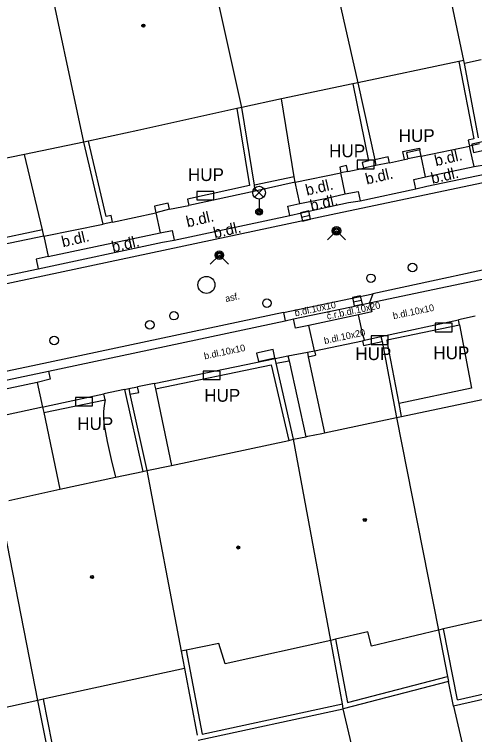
# Model space of a CAD drawing. Extents: x -596229 to -595156, y -1161237 to -1159376.
# Drawn here: x -595714.95 to -595687.89, y -1161008.44 to -1160966.09 of the extents above; entities that cross this region are included whole.
import ezdxf

# ---------------------------------------------------------------- set-up
doc = ezdxf.new("R2010")
doc.units = 0
for name, color, linetype in [('DOP - kresba z DSPS bez souradnic', 7, 'Continuous'), ('DOP - rozhrani ploch obecne', 7, 'Continuous'), ('Level 24', 7, 'Continuous'), ('Level 27', 7, 'Continuous'), ('Level 28', 7, 'Continuous'), ('Level 31', 7, 'Continuous'), ('Level 33', 7, 'Continuous'), ('Level 39', 7, 'Continuous'), ('plynovod - povrch.  znaky - PRIS skut. velikost', 7, 'Continuous'), ('Specificka linie pasportu komunikaci', 7, 'Continuous'), ('TM - budovy zdene_ betonove - VP', 7, 'Continuous'), ('TM - komunikace - VP', 7, 'Continuous'), ('TM - letecke snimky - pomocna linie', 7, 'Continuous'), ('TM - plot drateny_ kovovy - VP', 7, 'Continuous'), ('TM - plot dreveny - VP', 7, 'Continuous'), ('TM - plot zdeny_ ohradni zed - VP', 7, 'Continuous'), ('TM - podezdivka plotu - VP', 7, 'Continuous'), ('TM - popis objektu', 7, 'Continuous'), ('TM - popis povrchu', 7, 'Continuous'), ('TM - rozhrani mezi zpev. plochami mezi sebou - VP', 7, 'Continuous'), ('TM - rozhrani ploch obecne - VP', 7, 'Continuous'), ('TM - vjezd na pozemek', 7, 'Continuous')]:
    doc.layers.add(name, color=color, linetype=linetype)

msp = doc.modelspace()

# ---------------------------------------------------------------- linework, layer by layer
at = {"layer": 'DOP - kresba z DSPS bez souradnic'}
for points in [[(-595688.9, -1161006.41), (-595689.72, -1161002.23)], [(-595696.06, -1161002.84), (-595695.37, -1161006.56)], [(-595704.85, -1161003.47), (-595703.91, -1161008.41)], [(-595688.9, -1161006.41), (-595679.06, -1161004.17)], [(-595695.37, -1161006.56), (-595689.48, -1161005.02)], [(-595713.27, -1161006.37), (-595712.5, -1161010.25)], [(-595703.91, -1161008.41), (-595695.66, -1161006.64)]]:
    msp.add_lwpolyline(points, dxfattribs=at)
at = {"layer": 'DOP - rozhrani ploch obecne'}
for points in [[(-595690.01, -1161002.3), (-595689.48, -1161005.02)], [(-595695.66, -1161006.64), (-595696.35, -1161002.91)], [(-595704.95, -1161004.56), (-595704.21, -1161008.48)], [(-595679, -1161004.47), (-595689.13, -1161006.77)], [(-595689.48, -1161005.02), (-595689.42, -1161005.32)], [(-595689.42, -1161005.32), (-595695.61, -1161006.93)], [(-595689.13, -1161006.77), (-595689.42, -1161005.32)], [(-595712.81, -1161010.26), (-595713.57, -1161006.43)], [(-595695.61, -1161006.93), (-595695.66, -1161006.64)], [(-595689.13, -1161006.77), (-595685.09, -1161024.14)], [(-595704.15, -1161008.77), (-595695.61, -1161006.93)], [(-595691.15, -1161025.87), (-595695.61, -1161006.93)]]:
    msp.add_lwpolyline(points, dxfattribs=at)
at = {"layer": 'Level 24'}
for points in [[(-595687.944, -1160974.213), (-595686.968, -1160973.995), (-595687.076, -1160973.507), (-595688.052, -1160973.725)], [(-595694.798, -1160975.169), (-595693.798, -1160975.169), (-595693.798, -1160974.669), (-595694.798, -1160974.669)], [(-595704.218, -1160976.999), (-595703.218, -1160976.999), (-595703.218, -1160976.499), (-595704.218, -1160976.499)], [(-595690.198, -1160984.749), (-595689.198, -1160984.749), (-595689.198, -1160984.249), (-595690.198, -1160984.249)], [(-595693.978, -1160985.499), (-595692.978, -1160985.499), (-595692.978, -1160984.999), (-595693.978, -1160984.999)], [(-595700.604, -1160986.503), (-595699.628, -1160986.285), (-595699.736, -1160985.797), (-595700.712, -1160986.015)], [(-595703.858, -1160987.569), (-595702.858, -1160987.569), (-595702.858, -1160987.069), (-595703.858, -1160987.069)], [(-595711.358, -1160989.119), (-595710.358, -1160989.119), (-595710.358, -1160988.619), (-595711.358, -1160988.619)]]:
    msp.add_lwpolyline(points, close=True, dxfattribs=at)
at = {"layer": 'Level 27'}
for p, q in [((-595698.074, -1160978.006), (-595697.586, -1160977.894)), ((-595695.025, -1160982.992), (-595694.535, -1160982.888))]:
    msp.add_line(p, q, dxfattribs=at)
for points in [[(-595698.017, -1160978.25), (-595697.53, -1160978.137), (-595697.643, -1160977.65), (-595698.13, -1160977.763)], [(-595694.973, -1160983.236), (-595694.484, -1160983.133), (-595694.587, -1160982.644), (-595695.076, -1160982.747)]]:
    msp.add_lwpolyline(points, close=True, dxfattribs=at)
msp.add_circle((-595703.66, -1160982), 0.5, dxfattribs=at)
at = {"layer": 'Level 28'}
for centre in [(-595691.54, -1160980.97), (-595693.98, -1160981.61), (-595700.1, -1160983.07), (-595705.57, -1160983.81), (-595706.99, -1160984.35), (-595712.62, -1160985.27)]:
    msp.add_circle(centre, 0.25, dxfattribs=at)
at = {"layer": 'Level 31'}
for points in [[(-595696.54, -1160979.35), (-595696.01, -1160978.82), (-595695.48, -1160979.35)], [(-595703.43, -1160980.78), (-595702.9, -1160980.25), (-595702.37, -1160980.78)]]:
    msp.add_lwpolyline(points, dxfattribs=at)
for centre, radius in [((-595696.01, -1160978.82), 0.25), ((-595696.01, -1160978.82), 0.18), ((-595696.01, -1160978.82), 0.11), ((-595702.9, -1160980.25), 0.25), ((-595702.9, -1160980.25), 0.18), ((-595702.9, -1160980.25), 0.11)]:
    msp.add_circle(centre, radius, dxfattribs=at)
at = {"layer": 'Level 33'}
for p, q in [((-595700.825, -1160976.84), (-595700.295, -1160976.31)), ((-595700.825, -1160976.31), (-595700.295, -1160976.84)), ((-595700.56, -1160976.95), (-595700.56, -1160977.7))]:
    msp.add_line(p, q, dxfattribs=at)
for centre, radius in [((-595700.56, -1160976.575), 0.375), ((-595700.56, -1160977.7), 0.2), ((-595700.56, -1160977.7), 0.145), ((-595700.56, -1160977.7), 0.0876)]:
    msp.add_circle(centre, radius, dxfattribs=at)
at = {"layer": 'Level 39'}
for centre, radius in [((-595707.37, -1160966.75), 0.09), ((-595707.37, -1160966.75), 0.0398), ((-595694.34, -1160995.82), 0.09), ((-595694.34, -1160995.82), 0.0398), ((-595701.79, -1160997.44), 0.09), ((-595701.79, -1160997.44), 0.0398), ((-595710.39, -1160999.18), 0.09), ((-595710.39, -1160999.18), 0.0398)]:
    msp.add_circle(centre, radius, dxfattribs=at)
at = {"layer": 'plynovod - povrch.  znaky - PRIS skut. velikost'}
msp.add_lwpolyline([(-595692.01, -1160974.62), (-595692.1, -1160974.16), (-595691.12, -1160973.95), (-595691.1, -1160974.06)], dxfattribs=at)
at = {"layer": 'Specificka linie pasportu komunikaci'}
for points in [[(-595693.87, -1160982.52), (-595694.06, -1160983.06)], [(-595699.13, -1160983.63), (-595699.03, -1160984.11)]]:
    msp.add_lwpolyline(points, dxfattribs=at)
at = {"layer": 'TM - budovy zdene_ betonove - VP'}
for points in [[(-595688.52, -1160968.8), (-595691, -1160956.97)], [(-595697.35, -1160958.68), (-595694.76, -1160970.11)], [(-595701.58, -1160971.56), (-595703.92, -1160960.96)], [(-595710.88, -1160973.61), (-595713.16, -1160962.85)], [(-595688.81, -1160968.86), (-595694.76, -1160970.11)], [(-595688.52, -1160968.8), (-595688.81, -1160968.86)], [(-595688.48, -1160968.97), (-595688.52, -1160968.8)], [(-595687.49, -1160968.76), (-595688.48, -1160968.97)], [(-595695.05, -1160970.17), (-595699.24, -1160971.06)], [(-595694.76, -1160970.11), (-595695.05, -1160970.17)], [(-595699.24, -1160971.06), (-595701.58, -1160971.56)], [(-595701.58, -1160971.56), (-595701.88, -1160971.63)], [(-595701.88, -1160971.63), (-595707.69, -1160972.91)], [(-595707.69, -1160972.91), (-595710.59, -1160973.55)], [(-595710.88, -1160973.61), (-595714.36, -1160974.33)], [(-595710.59, -1160973.55), (-595710.88, -1160973.61)], [(-595714.45, -1160974.35), (-595720.27, -1160975.55)], [(-595714.36, -1160974.33), (-595714.45, -1160974.35)], [(-595692.19, -1160989.74), (-595682.22, -1160987.64)], [(-595696.87, -1160990.73), (-595696.71, -1160990.7), (-595692.48, -1160989.8)], [(-595692.48, -1160989.8), (-595692.19, -1160989.74)], [(-595692.48, -1160989.8), (-595690.01, -1161002.3)], [(-595698.82, -1160991.14), (-595698.53, -1160991.08)], [(-595698.53, -1160991.08), (-595697.82, -1160990.93), (-595697.7, -1160990.9)], [(-595696.35, -1161002.91), (-595698.53, -1160991.08)], [(-595697.7, -1160990.9), (-595696.87, -1160990.73)], [(-595705.72, -1160992.61), (-595698.82, -1160991.14)], [(-595707.17, -1160992.92), (-595705.72, -1160992.61)], [(-595709, -1160993.31), (-595707.41, -1160992.97)], [(-595707.41, -1160992.97), (-595707.17, -1160992.92)], [(-595707.17, -1160992.92), (-595705.15, -1161003.53)], [(-595712.28, -1160994.02), (-595709, -1160993.31)], [(-595715.28, -1160994.67), (-595712.28, -1160994.02)], [(-595713.57, -1161006.43), (-595715.87, -1160994.79)], [(-595679.87, -1161000), (-595689.72, -1161002.23)], [(-595694.17, -1161002.41), (-595696.06, -1161002.84)], [(-595693.94, -1161003.24), (-595694.17, -1161002.41)], [(-595690.01, -1161002.3), (-595693.94, -1161003.24)], [(-595689.72, -1161002.23), (-595690.01, -1161002.3)], [(-595696.35, -1161002.91), (-595702.55, -1161004.28)], [(-595696.06, -1161002.84), (-595696.35, -1161002.91)], [(-595702.92, -1161003.09), (-595704.85, -1161003.47)], [(-595702.55, -1161004.28), (-595702.92, -1161003.09)], [(-595704.85, -1161003.47), (-595705.15, -1161003.53)], [(-595705.15, -1161003.53), (-595704.95, -1161004.56)], [(-595704.95, -1161004.56), (-595713.27, -1161006.37)], [(-595713.57, -1161006.43), (-595721.99, -1161008.28)], [(-595713.27, -1161006.37), (-595713.57, -1161006.43)]]:
    msp.add_lwpolyline(points, dxfattribs=at)
at = {"layer": 'TM - komunikace - VP'}
for points in [[(-595691.35, -1160976.35), (-595690.7, -1160976.19), (-595687.77, -1160975.59), (-595687.07, -1160975.45)], [(-595694.62, -1160977.05), (-595691.35, -1160976.35)], [(-595698.75, -1160977.92), (-595698.06, -1160977.76), (-595696.47, -1160977.41), (-595695.31, -1160977.16), (-595694.62, -1160977.05)], [(-595705.56, -1160979.36), (-595698.75, -1160977.92)], [(-595713.55, -1160981.05), (-595706.25, -1160979.48), (-595705.56, -1160979.36)], [(-595694.06, -1160983.06), (-595680.73, -1160980.25)], [(-595718.72, -1160982.14), (-595713.55, -1160981.05)], [(-595699.03, -1160984.11), (-595698.53, -1160983.99), (-595698.06, -1160983.9), (-595695.12, -1160983.28), (-595694.15, -1160983.08), (-595694.06, -1160983.06)], [(-595712.95, -1160987.07), (-595699.03, -1160984.11)], [(-595729.49, -1160990.57), (-595712.95, -1160987.07)]]:
    msp.add_lwpolyline(points, dxfattribs=at)
at = {"layer": 'TM - letecke snimky - pomocna linie'}
for points in [[(-595698.5, -1160975.64), (-595699.24, -1160971.06)], [(-595713.31, -1160978.75), (-595714.36, -1160974.33)], [(-595688.77, -1160984.34), (-595688.07, -1160988.08), (-595692.33, -1160988.98)], [(-595697.67, -1160986.23), (-595696.71, -1160990.7)], [(-595698.8, -1160986.46), (-595697.82, -1160990.93)], [(-595706.66, -1160988.12), (-595705.72, -1160992.61)], [(-595709.62, -1160988.75), (-595709.68, -1160989.09), (-595709.72, -1160989.44), (-595709.72, -1160989.79), (-595709.7, -1160990.14)], [(-595713.23, -1160989.51), (-595712.28, -1160994.02)], [(-595709.7, -1160990.14), (-595709.49, -1160991.2), (-595709.26, -1160992.26), (-595709, -1160993.31)]]:
    msp.add_lwpolyline(points, dxfattribs=at)
at = {"layer": 'TM - plot drateny_ kovovy - VP'}
for points in [[(-595688.81, -1160968.86), (-595687.93, -1160973.41), (-595688.26, -1160973.49), (-595688.18, -1160973.83)], [(-595701.88, -1160971.63), (-595701.12, -1160976.16)], [(-595709.18, -1160978.3), (-595709.27, -1160977.92), (-595709.55, -1160977.98), (-595710.59, -1160973.55)], [(-595691.1, -1160974.06), (-595691.9, -1160974.23), (-595691.82, -1160974.58)], [(-595691.03, -1160974.42), (-595691.1, -1160974.06)], [(-595692.9, -1160974.81), (-595692.97, -1160974.46), (-595693.76, -1160974.64)], [(-595701.12, -1160976.16), (-595704.78, -1160976.95), (-595704.7, -1160977.33)], [(-595705.83, -1160977.55), (-595705.91, -1160977.2), (-595706.72, -1160977.37), (-595706.64, -1160977.75)], [(-595688.77, -1160984.34), (-595688.83, -1160984.05)], [(-595693.03, -1160985.23), (-595688.77, -1160984.34)], [(-595692.33, -1160988.98), (-595693, -1160985.4), (-595693.03, -1160985.23)], [(-595706.66, -1160988.12), (-595699.86, -1160986.69), (-595698.82, -1160991.14)], [(-595708.16, -1160988.43), (-595707.64, -1160988.33), (-595707.71, -1160987.99)], [(-595706.73, -1160987.79), (-595706.66, -1160988.12)], [(-595709.62, -1160988.75), (-595709.69, -1160988.41)], [(-595708.47, -1160988.15), (-595707.41, -1160992.97)], [(-595713.23, -1160989.51), (-595709.62, -1160988.75)], [(-595692.19, -1160989.74), (-595692.33, -1160988.98)], [(-595713.31, -1160989.19), (-595713.23, -1160989.51)]]:
    msp.add_lwpolyline(points, dxfattribs=at)
at = {"layer": 'TM - plot dreveny - VP'}
for points in [[(-595695.05, -1160970.17), (-595694.12, -1160974.71)], [(-595695.35, -1160975.32), (-595695.42, -1160974.98), (-595695.82, -1160975.07), (-595695.75, -1160975.41)], [(-595694.12, -1160974.71), (-595694.49, -1160974.79), (-595694.42, -1160975.13)], [(-595698.5, -1160975.64), (-595700.84, -1160976.13)], [(-595698.43, -1160975.95), (-595698.5, -1160975.64)], [(-595713.31, -1160978.75), (-595719.25, -1160980.02)], [(-595713.22, -1160979.13), (-595713.31, -1160978.75)]]:
    msp.add_lwpolyline(points, dxfattribs=at)
at = {"layer": 'TM - plot zdeny_ ohradni zed - VP'}
for points in [[(-595694.42, -1160985.56), (-595693.33, -1160985.33)], [(-595697.67, -1160986.23), (-595697.24, -1160986.14)], [(-595699.55, -1160986.61), (-595698.8, -1160986.46)]]:
    msp.add_lwpolyline(points, dxfattribs=at)
at = {"layer": 'TM - podezdivka plotu - VP'}
for points in [[(-595687.66, -1160973.35), (-595688.48, -1160968.97)], [(-595694.76, -1160970.11), (-595693.76, -1160974.64)], [(-595700.84, -1160976.13), (-595701.58, -1160971.56)], [(-595709.74, -1160978.42), (-595710.88, -1160973.61)], [(-595687.6, -1160973.7), (-595688.18, -1160973.83)], [(-595691.03, -1160974.42), (-595691.82, -1160974.58)], [(-595693.69, -1160974.97), (-595694.42, -1160975.13)], [(-595693.76, -1160974.64), (-595693.69, -1160974.97)], [(-595692.9, -1160974.81), (-595693.69, -1160974.97)], [(-595695.35, -1160975.32), (-595695.75, -1160975.41)], [(-595700.79, -1160976.49), (-595700.84, -1160976.13)], [(-595698.43, -1160975.95), (-595700.79, -1160976.49)], [(-595700.79, -1160976.49), (-595704.7, -1160977.33)], [(-595705.83, -1160977.55), (-595706.64, -1160977.75)], [(-595709.18, -1160978.3), (-595709.74, -1160978.42)], [(-595713.22, -1160979.13), (-595719.18, -1160980.36)], [(-595693.41, -1160985.03), (-595688.83, -1160984.05)], [(-595694.48, -1160985.28), (-595694.37, -1160985.25), (-595693.41, -1160985.03)], [(-595693.41, -1160985.03), (-595693.33, -1160985.33)], [(-595694.48, -1160985.28), (-595694.42, -1160985.56)], [(-595693.33, -1160985.33), (-595692.48, -1160989.8)], [(-595697.72, -1160985.95), (-595697.3, -1160985.87)], [(-595697.72, -1160985.95), (-595697.67, -1160986.23)], [(-595697.3, -1160985.87), (-595697.24, -1160986.14)], [(-595706.73, -1160987.79), (-595699.61, -1160986.33)], [(-595699.61, -1160986.33), (-595698.87, -1160986.17)], [(-595698.53, -1160991.08), (-595699.55, -1160986.61), (-595699.61, -1160986.33)], [(-595698.87, -1160986.17), (-595698.8, -1160986.46)], [(-595708.47, -1160988.15), (-595708.23, -1160988.1)], [(-595708.23, -1160988.1), (-595707.71, -1160987.99)], [(-595708.23, -1160988.1), (-595708.16, -1160988.43)], [(-595713.31, -1160989.19), (-595713.07, -1160989.13), (-595709.69, -1160988.41)], [(-595708.16, -1160988.43), (-595707.17, -1160992.92)]]:
    msp.add_lwpolyline(points, dxfattribs=at)
at = {"layer": 'TM - rozhrani mezi zpev. plochami mezi sebou - VP'}
for points in [[(-595694.06, -1160983.06), (-595693.93, -1160983.58), (-595694.71, -1160983.76), (-595697.64, -1160984.38), (-595698.42, -1160984.54), (-595698.53, -1160983.99)], [(-595694.37, -1160985.25), (-595694.45, -1160984.92), (-595694.71, -1160983.76)], [(-595697.3, -1160985.87), (-595697.64, -1160984.38)]]:
    msp.add_lwpolyline(points, dxfattribs=at)
at = {"layer": 'TM - rozhrani ploch obecne - VP'}
for points in [[(-595664.27, -1160970.63), (-595664.17, -1160971.12), (-595679.65, -1160974.36), (-595696.33, -1160977.88), (-595714.85, -1160981.82), (-595732.56, -1160985.58), (-595732.97, -1160985.67), (-595733.07, -1160985.18)], [(-595687.92, -1160975.04), (-595688.18, -1160973.83)], [(-595690.78, -1160975.64), (-595691.03, -1160974.42)], [(-595687.92, -1160975.04), (-595687.19, -1160974.91), (-595687.07, -1160975.45)], [(-595695.49, -1160976.65), (-595695.75, -1160975.41)], [(-595690.78, -1160975.64), (-595687.92, -1160975.04)], [(-595691.35, -1160976.35), (-595691.46, -1160975.79), (-595690.78, -1160975.64)], [(-595698.17, -1160977.21), (-595698.43, -1160975.95)], [(-595698.17, -1160977.21), (-595696.57, -1160976.89), (-595695.49, -1160976.65)], [(-595695.49, -1160976.65), (-595694.73, -1160976.51), (-595694.62, -1160977.05)], [(-595698.75, -1160977.92), (-595698.87, -1160977.36), (-595698.17, -1160977.21)], [(-595706.64, -1160977.75), (-595706.39, -1160978.94)], [(-595670.6, -1160977.58), (-595684.25, -1160980.44), (-595693.87, -1160982.52)], [(-595706.39, -1160978.94), (-595705.68, -1160978.79), (-595705.56, -1160979.36)], [(-595713.22, -1160979.13), (-595712.97, -1160980.33)], [(-595712.97, -1160980.33), (-595706.39, -1160978.94)], [(-595712.97, -1160980.33), (-595713.67, -1160980.48), (-595713.55, -1160981.05)], [(-595699.13, -1160983.63), (-595693.87, -1160982.52)], [(-595699.13, -1160983.63), (-595713.6, -1160986.69), (-595729.6, -1160990.08), (-595729.49, -1160990.57)], [(-595712.95, -1160987.07), (-595712.85, -1160987.55), (-595713.62, -1160987.74)], [(-595713.62, -1160987.74), (-595728.81, -1160990.95)], [(-595713.62, -1160987.74), (-595713.31, -1160989.19)]]:
    msp.add_lwpolyline(points, dxfattribs=at)
at = {"layer": 'TM - vjezd na pozemek'}
for points in [[(-595691.03, -1160974.42), (-595688.18, -1160973.83)], [(-595692.01, -1160974.62), (-595691.82, -1160974.58)], [(-595692.9, -1160974.81), (-595692.01, -1160974.62)], [(-595698.43, -1160975.95), (-595695.75, -1160975.41)], [(-595695.35, -1160975.32), (-595694.42, -1160975.13)], [(-595705.83, -1160977.55), (-595704.7, -1160977.33)], [(-595709.18, -1160978.3), (-595706.64, -1160977.75)], [(-595713.22, -1160979.13), (-595709.74, -1160978.42)], [(-595687.85, -1160983.84), (-595688.83, -1160984.05)], [(-595697.3, -1160985.87), (-595694.48, -1160985.28)], [(-595698.87, -1160986.17), (-595697.72, -1160985.95)], [(-595706.73, -1160987.79), (-595707.71, -1160987.99)], [(-595708.47, -1160988.15), (-595709.69, -1160988.41)], [(-595713.31, -1160989.19), (-595716.31, -1160989.83)]]:
    msp.add_lwpolyline(points, dxfattribs=at)

# ---------------------------------------------------------------- texts
at = {"layer": 'TM - popis objektu'}
for p in [(-595692.35, -1160973.59), (-595696.44, -1160974.49), (-595704.75, -1160975.89), (-595694.9, -1160986.42), (-595690.31, -1160986.37), (-595703.79, -1160988.87), (-595711.26, -1160990.53)]:
    msp.add_text('HUP', height=0.75, dxfattribs=at).set_placement(p)
at = {"layer": 'TM - popis povrchu'}
for s, height, rotation, p in [('b.dl.', 0.65, 13.11, (-595690.16, -1160975.02)), ('b.dl.', 0.65, 13.11, (-595694.23, -1160976.1)), ('b.dl.', 0.65, 13.11, (-595690.37, -1160976.06)), ('b.dl.', 0.65, 13.11, (-595697.75, -1160976.75)), ('b.dl.', 0.65, 13.11, (-595697.48, -1160977.66)), ('b.dl.', 0.65, 13.11, (-595704.77, -1160978.62)), ('b.dl.', 0.65, 13.11, (-595703.17, -1160979.27)), ('b.dl.', 0.65, 13.11, (-595712.1, -1160979.79)), ('b.dl.', 0.65, 13.11, (-595709.15, -1160980.09)), ('asf.', 0.4, 11.8356, (-595702.52, -1160983.01)), ('b.dl.10x10', 0.4, 11.8356, (-595698.43, -1160983.85)), ('č.r.b.dl.10x20', 0.4, 12, (-595696.54, -1160984.04)), ('b.dl.10x10', 0.4, 11.8356, (-595692.65, -1160984.02)), ('b.dl.10x20', 0.4, 12, (-595696.7, -1160985.48)), ('b.dl.10x10', 0.4, 11.8356, (-595703.76, -1160986.38))]:
    msp.add_text(s, height=height, rotation=rotation, dxfattribs=at).set_placement(p)

doc.saveas('drawing.dxf')
